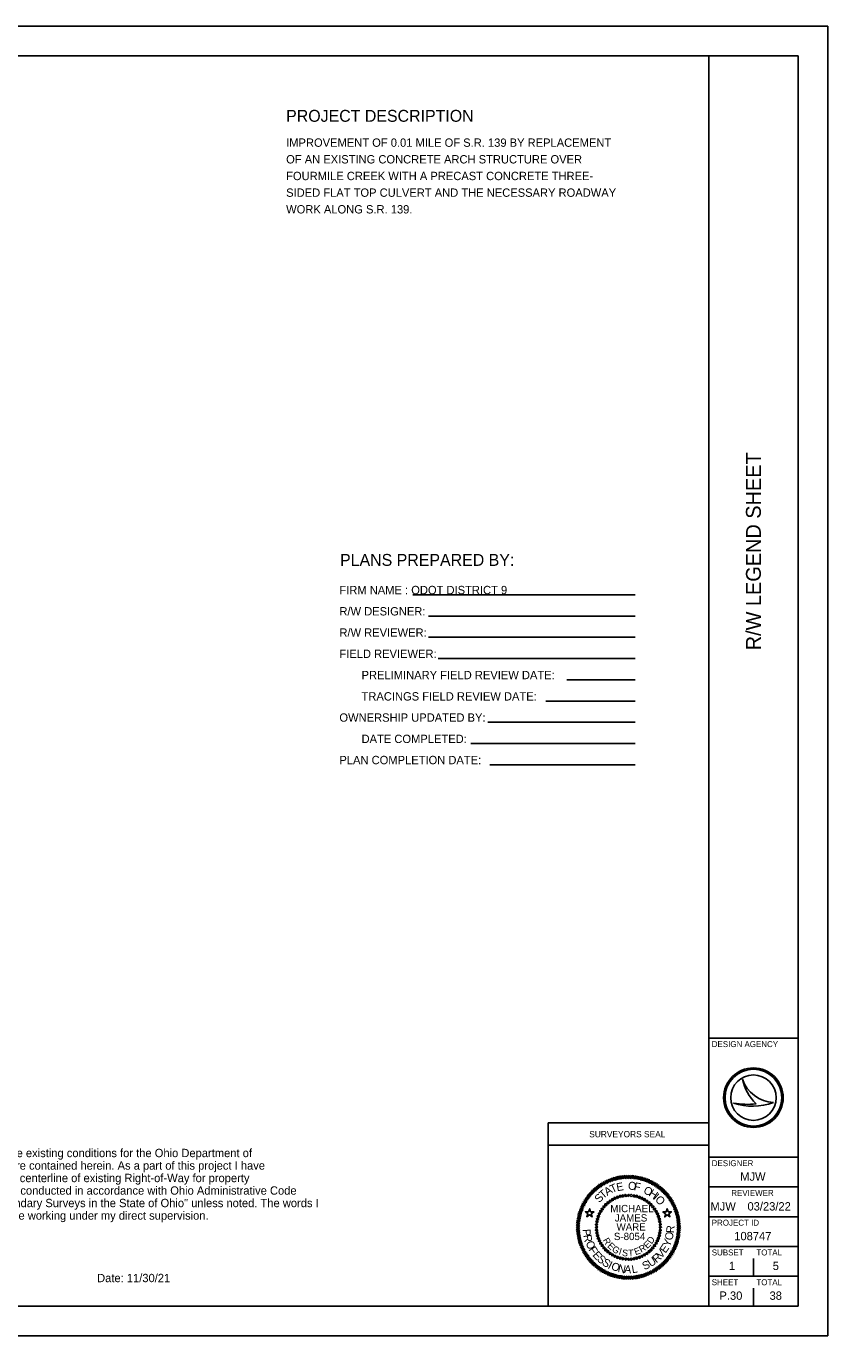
# Model space of a CAD drawing. Extents: x 0 to 34, y -5.8 to 22.
# Drawn here: x 20.53 to 34, y 0 to 22 of the extents above; entities that cross this region are included whole.
import ezdxf

# ---------------------------------------------------------------- set-up
doc = ezdxf.new("R2010")
doc.units = 0
for name, color, linetype in [('SH_Border', 7, 'Continuous'), ('SH_Cut_Line', 7, 'Continuous'), ('SH_Data', 7, 'Continuous'), ('SH_Text', 7, 'Continuous')]:
    doc.layers.add(name, color=color, linetype=linetype)

msp = doc.modelspace()

# ---------------------------------------------------------------- linework, layer by layer
at = {"layer": 'SH_Border'}
for p, q in [((32, 0.5), (32, 21.5)), ((32, 5), (33.5, 5)), ((32, 3), (33.5, 3)), ((32, 2.5), (33.5, 2.5)), ((32, 2), (33.5, 2)), ((32, 1.5), (33.5, 1.5)), ((32, 1), (33.5, 1))]:
    msp.add_line(p, q, dxfattribs=at)
msp.add_lwpolyline([(1.5, 21.5), (33.5, 21.5), (33.5, 0.5), (1.5, 0.5)], close=True, dxfattribs=at)
at = {"layer": 'SH_Cut_Line'}
msp.add_lwpolyline([(0, 0), (34, 0), (34, 22), (0, 22)], close=True, dxfattribs=at)
at = {"layer": 'SH_Data'}
for p, q in [((32.567, 4.31), (32.567, 4.31)), ((32.75, 4), (32.75, 4)), ((32.417, 3.91), (32.417, 3.91)), ((33.087, 3.919), (33.087, 3.919)), ((29.3, 3.2), (32, 3.2)), ((32.75, 1), (32.75, 1.3)), ((32.375, 0.675), (32.375, 0.675)), ((32.75, 0.5), (32.75, 0.8))]:
    msp.add_line(p, q, dxfattribs=at)
msp.add_lwpolyline([(29.3, 3.575), (32, 3.575), (32, 0.5), (29.3, 0.5)], close=True, dxfattribs=at)
for radius in [0.5, 0.477, 0.477, 0.382]:
    msp.add_circle((32.75, 4), radius, dxfattribs=at)
for centre, radius, start, end in [((33.116, 4.498), 0.58, 198.9257, 198.9319), ((33.347, 4.47), 0.796, 191.6379, 191.6421), ((33.116, 4.498), 0.58, 198.9319, 267.1657), ((33.347, 4.47), 0.796, 191.6421, 226.0947), ((32.739, 4.87), 1.013, 251.4576, 290.0832), ((32.648, 5.154), 1.266, 259.4964, 259.4995), ((32.739, 4.87), 1.013, 251.4527, 251.4576), ((32.648, 5.154), 1.266, 259.4995, 276.6672)]:
    msp.add_arc(centre, radius, start, end, dxfattribs=at)
at = {"layer": 'SH_Text'}
for p, q in [((27.026, 12.449), (30.763, 12.449)), ((27.29, 12.091), (30.763, 12.091)), ((27.29, 11.734), (30.763, 11.734)), ((27.454, 11.377), (30.763, 11.377)), ((29.617, 11.02), (30.763, 11.02)), ((29.26, 10.663), (30.763, 10.663)), ((28.29, 10.306), (30.763, 10.306)), ((28.004, 9.948), (30.763, 9.948)), ((28.319, 9.592), (30.763, 9.592)), ((30.381, 2.593), (30.338, 2.644)), ((30.408, 2.602), (30.367, 2.655)), ((30.436, 2.61), (30.396, 2.664)), ((30.463, 2.617), (30.426, 2.672)), ((30.491, 2.623), (30.456, 2.68)), ((30.519, 2.628), (30.486, 2.686)), ((30.547, 2.632), (30.516, 2.691)), ((30.576, 2.635), (30.546, 2.695)), ((30.604, 2.637), (30.577, 2.698)), ((30.633, 2.638), (30.608, 2.7)), ((30.661, 2.638), (30.638, 2.701)), ((30.69, 2.638), (30.669, 2.701)), ((30.718, 2.636), (30.699, 2.7)), ((30.746, 2.633), (30.73, 2.698)), ((30.774, 2.629), (30.761, 2.694)), ((30.803, 2.624), (30.791, 2.69)), ((30.83, 2.618), (30.821, 2.684)), ((30.858, 2.611), (30.851, 2.678)), ((30.885, 2.604), (30.881, 2.67)), ((30.913, 2.595), (30.91, 2.662)), ((30.939, 2.585), (30.939, 2.652)), ((30.966, 2.575), (30.968, 2.642)), ((30.071, 2.398), (30.01, 2.425)), ((30.091, 2.417), (30.031, 2.447)), ((30.112, 2.437), (30.053, 2.468)), ((30.134, 2.455), (30.076, 2.488)), ((30.156, 2.473), (30.1, 2.508)), ((30.179, 2.489), (30.124, 2.527)), ((30.203, 2.505), (30.149, 2.545)), ((30.227, 2.521), (30.174, 2.562)), ((30.252, 2.535), (30.2, 2.578)), ((30.277, 2.548), (30.227, 2.593)), ((30.302, 2.561), (30.254, 2.607)), ((30.328, 2.573), (30.282, 2.621)), ((30.355, 2.583), (30.31, 2.633)), ((30.992, 2.563), (30.997, 2.63)), ((31.018, 2.551), (31.025, 2.617)), ((31.043, 2.538), (31.052, 2.604)), ((31.067, 2.523), (31.079, 2.589)), ((31.092, 2.508), (31.106, 2.574)), ((31.115, 2.493), (31.132, 2.557)), ((31.138, 2.476), (31.157, 2.54)), ((31.161, 2.458), (31.182, 2.522)), ((31.183, 2.44), (31.206, 2.503)), ((31.204, 2.421), (31.229, 2.483)), ((31.225, 2.402), (31.252, 2.463)), ((31.244, 2.381), (31.274, 2.441)), ((29.935, 2.216), (29.868, 2.225)), ((29.949, 2.24), (29.883, 2.252)), ((29.964, 2.265), (29.898, 2.279)), ((29.98, 2.288), (29.915, 2.304)), ((29.996, 2.311), (29.932, 2.33)), ((30.014, 2.334), (29.95, 2.355)), ((30.032, 2.356), (29.969, 2.379)), ((30.051, 2.377), (29.989, 2.402)), ((31.264, 2.36), (31.295, 2.419)), ((31.282, 2.338), (31.315, 2.396)), ((31.3, 2.316), (31.335, 2.373)), ((31.316, 2.293), (31.354, 2.348)), ((31.332, 2.269), (31.372, 2.323)), ((31.348, 2.245), (31.389, 2.298)), ((31.362, 2.221), (31.405, 2.272)), ((31.375, 2.195), (31.42, 2.245)), ((31.388, 2.17), (31.434, 2.218)), ((29.854, 2.003), (29.788, 1.994)), ((29.861, 2.031), (29.794, 2.024)), ((29.868, 2.058), (29.802, 2.054)), ((29.877, 2.086), (29.81, 2.083)), ((29.887, 2.112), (29.82, 2.112)), ((29.897, 2.139), (29.831, 2.141)), ((29.909, 2.165), (29.842, 2.17)), ((29.921, 2.19), (29.855, 2.197)), ((31.4, 2.144), (31.448, 2.19)), ((31.41, 2.118), (31.46, 2.162)), ((31.42, 2.091), (31.471, 2.134)), ((31.429, 2.064), (31.482, 2.105)), ((31.437, 2.036), (31.491, 2.076)), ((31.444, 2.009), (31.499, 2.046)), ((31.45, 1.981), (31.507, 2.016)), ((31.455, 1.953), (31.513, 1.986)), ((29.835, 1.862), (29.771, 1.842)), ((29.834, 1.834), (29.771, 1.811)), ((29.836, 1.891), (29.772, 1.872)), ((29.834, 1.805), (29.772, 1.78)), ((29.839, 1.919), (29.774, 1.903)), ((29.835, 1.777), (29.774, 1.75)), ((29.843, 1.947), (29.778, 1.934)), ((29.848, 1.975), (29.782, 1.964)), ((31.459, 1.925), (31.518, 1.956)), ((31.462, 1.896), (31.522, 1.926)), ((31.463, 1.754), (31.527, 1.773)), ((31.464, 1.868), (31.525, 1.895)), ((31.465, 1.84), (31.527, 1.865)), ((31.465, 1.783), (31.528, 1.803)), ((31.466, 1.811), (31.528, 1.834)), ((29.837, 1.749), (29.777, 1.719)), ((29.84, 1.72), (29.781, 1.689)), ((29.844, 1.692), (29.786, 1.659)), ((29.849, 1.664), (29.792, 1.629)), ((29.855, 1.636), (29.8, 1.599)), ((29.862, 1.609), (29.808, 1.569)), ((29.87, 1.581), (29.817, 1.54)), ((29.879, 1.554), (29.828, 1.511)), ((31.422, 1.56), (31.489, 1.562)), ((31.431, 1.587), (31.497, 1.591)), ((31.439, 1.614), (31.505, 1.621)), ((31.445, 1.642), (31.512, 1.651)), ((31.451, 1.67), (31.517, 1.681)), ((31.456, 1.698), (31.521, 1.712)), ((31.46, 1.726), (31.525, 1.742)), ((29.889, 1.527), (29.839, 1.483)), ((29.9, 1.501), (29.851, 1.455)), ((29.911, 1.475), (29.865, 1.427)), ((29.924, 1.45), (29.879, 1.4)), ((29.937, 1.424), (29.894, 1.373)), ((29.952, 1.4), (29.91, 1.347)), ((29.967, 1.376), (29.927, 1.322)), ((29.983, 1.352), (29.945, 1.297)), ((30, 1.329), (29.964, 1.273)), ((31.303, 1.334), (31.367, 1.315)), ((31.32, 1.357), (31.385, 1.341)), ((31.335, 1.38), (31.401, 1.367)), ((31.35, 1.405), (31.416, 1.393)), ((31.365, 1.429), (31.431, 1.42)), ((31.378, 1.455), (31.444, 1.448)), ((31.39, 1.48), (31.457, 1.476)), ((31.402, 1.506), (31.469, 1.504)), ((31.412, 1.533), (31.479, 1.533)), ((30.017, 1.307), (29.984, 1.249)), ((30.036, 1.285), (30.004, 1.226)), ((30.055, 1.264), (30.025, 1.204)), ((30.075, 1.244), (30.047, 1.182)), ((30.095, 1.224), (30.07, 1.162)), ((30.116, 1.205), (30.094, 1.142)), ((30.138, 1.187), (30.118, 1.123)), ((30.161, 1.169), (30.142, 1.105)), ((30.184, 1.152), (30.168, 1.088)), ((30.208, 1.137), (30.194, 1.071)), ((30.232, 1.122), (30.22, 1.056)), ((30.256, 1.107), (30.247, 1.041)), ((31.048, 1.11), (31.099, 1.067)), ((31.072, 1.125), (31.125, 1.083)), ((31.096, 1.14), (31.15, 1.1)), ((31.12, 1.156), (31.175, 1.118)), ((31.143, 1.173), (31.2, 1.137)), ((31.165, 1.19), (31.223, 1.157)), ((31.187, 1.209), (31.246, 1.177)), ((31.208, 1.228), (31.268, 1.198)), ((31.229, 1.248), (31.29, 1.22)), ((31.248, 1.268), (31.31, 1.243)), ((31.267, 1.289), (31.33, 1.266)), ((31.286, 1.311), (31.349, 1.291)), ((30.282, 1.094), (30.275, 1.028)), ((30.307, 1.082), (30.303, 1.015)), ((30.333, 1.07), (30.331, 1.003)), ((30.36, 1.06), (30.36, 0.993)), ((30.387, 1.05), (30.389, 0.983)), ((30.414, 1.041), (30.418, 0.975)), ((30.441, 1.034), (30.448, 0.967)), ((30.469, 1.027), (30.478, 0.961)), ((30.497, 1.021), (30.508, 0.955)), ((30.525, 1.016), (30.539, 0.951)), ((30.553, 1.012), (30.569, 0.947)), ((30.581, 1.009), (30.6, 0.945)), ((30.61, 1.008), (30.63, 0.944)), ((30.638, 1.007), (30.661, 0.944)), ((30.667, 1.007), (30.692, 0.945)), ((30.695, 1.008), (30.722, 0.947)), ((30.724, 1.01), (30.753, 0.95)), ((30.752, 1.013), (30.783, 0.954)), ((30.78, 1.017), (30.813, 0.959)), ((30.808, 1.022), (30.843, 0.965)), ((30.836, 1.028), (30.873, 0.973)), ((30.864, 1.035), (30.903, 0.981)), ((30.891, 1.043), (30.932, 0.99)), ((30.918, 1.052), (30.961, 1.001)), ((30.945, 1.062), (30.989, 1.012)), ((30.971, 1.072), (31.017, 1.024)), ((30.997, 1.084), (31.045, 1.038)), ((31.023, 1.097), (31.072, 1.052))]:
    msp.add_line(p, q, dxfattribs=at)
for points in [[(30.285, 2.187), (30.285, 2.216), (30.256, 2.216), (30.256, 2.187)], [(30.318, 2.218), (30.32, 2.246), (30.292, 2.249), (30.29, 2.22)], [(30.354, 2.245), (30.358, 2.273), (30.331, 2.278), (30.326, 2.25)], [(30.392, 2.269), (30.399, 2.297), (30.372, 2.304), (30.364, 2.277)], [(30.431, 2.29), (30.441, 2.317), (30.415, 2.327), (30.405, 2.3)], [(30.473, 2.308), (30.485, 2.333), (30.459, 2.345), (30.447, 2.319)], [(30.516, 2.321), (30.53, 2.346), (30.506, 2.36), (30.492, 2.335)], [(30.56, 2.331), (30.576, 2.354), (30.553, 2.37), (30.537, 2.347)], [(30.605, 2.337), (30.623, 2.358), (30.601, 2.377), (30.583, 2.355)], [(30.65, 2.339), (30.67, 2.359), (30.65, 2.379), (30.63, 2.359)], [(30.695, 2.337), (30.716, 2.355), (30.698, 2.377), (30.676, 2.358)], [(30.739, 2.331), (30.762, 2.347), (30.746, 2.37), (30.723, 2.354)], [(30.783, 2.321), (30.808, 2.335), (30.794, 2.36), (30.769, 2.346)], [(30.826, 2.308), (30.852, 2.319), (30.84, 2.345), (30.814, 2.333)], [(30.868, 2.29), (30.894, 2.3), (30.885, 2.327), (30.858, 2.317)], [(30.908, 2.269), (30.935, 2.277), (30.928, 2.304), (30.9, 2.297)], [(30.946, 2.245), (30.973, 2.25), (30.969, 2.278), (30.941, 2.273)], [(30.981, 2.218), (31.01, 2.22), (31.007, 2.249), (30.979, 2.246)], [(31.015, 2.187), (31.043, 2.187), (31.043, 2.216), (31.015, 2.216)], [(30.015, 2.082), (30.07, 2.08), (30.024, 2.049), (30.04, 1.997), (29.996, 2.03), (29.951, 2), (29.97, 2.051), (29.927, 2.085), (29.981, 2.083), (30, 2.134)], [(30.151, 1.956), (30.137, 1.981), (30.112, 1.966), (30.127, 1.942)], [(30.165, 1.999), (30.153, 2.025), (30.127, 2.013), (30.139, 1.987)], [(30.182, 2.041), (30.172, 2.067), (30.146, 2.058), (30.155, 2.031)], [(30.203, 2.081), (30.195, 2.108), (30.168, 2.101), (30.175, 2.073)], [(30.227, 2.119), (30.222, 2.146), (30.194, 2.141), (30.199, 2.114)], [(30.254, 2.154), (30.252, 2.182), (30.224, 2.18), (30.226, 2.152)], [(31.045, 2.154), (31.073, 2.152), (31.076, 2.18), (31.047, 2.182)], [(31.072, 2.119), (31.1, 2.114), (31.105, 2.141), (31.077, 2.146)], [(31.097, 2.081), (31.124, 2.073), (31.131, 2.101), (31.104, 2.108)], [(31.117, 2.041), (31.144, 2.031), (31.154, 2.058), (31.127, 2.067)], [(31.135, 1.999), (31.16, 1.987), (31.172, 2.013), (31.147, 2.025)], [(31.148, 1.956), (31.173, 1.942), (31.187, 1.966), (31.162, 1.981)], [(31.303, 2.03), (31.26, 1.997), (31.275, 2.049), (31.229, 2.08), (31.284, 2.082), (31.299, 2.134), (31.318, 2.083), (31.373, 2.085), (31.329, 2.051), (31.348, 2)], [(30.134, 1.823), (30.114, 1.843), (30.094, 1.823), (30.114, 1.803)], [(30.135, 1.868), (30.117, 1.889), (30.096, 1.871), (30.114, 1.849)], [(30.135, 1.778), (30.114, 1.796), (30.096, 1.774), (30.117, 1.756)], [(30.141, 1.912), (30.125, 1.935), (30.102, 1.919), (30.118, 1.896)], [(31.158, 1.912), (31.181, 1.896), (31.197, 1.919), (31.174, 1.935)], [(31.164, 1.868), (31.185, 1.849), (31.204, 1.871), (31.182, 1.889)], [(31.164, 1.778), (31.182, 1.756), (31.204, 1.774), (31.185, 1.796)], [(31.166, 1.823), (31.186, 1.803), (31.206, 1.823), (31.186, 1.843)], [(30.141, 1.733), (30.118, 1.749), (30.102, 1.726), (30.125, 1.71)], [(30.151, 1.689), (30.127, 1.703), (30.112, 1.679), (30.137, 1.664)], [(30.165, 1.646), (30.139, 1.658), (30.127, 1.632), (30.153, 1.62)], [(30.182, 1.604), (30.155, 1.614), (30.146, 1.588), (30.172, 1.578)], [(30.203, 1.564), (30.175, 1.572), (30.168, 1.544), (30.195, 1.537)], [(31.097, 1.564), (31.104, 1.537), (31.131, 1.544), (31.124, 1.572)], [(31.117, 1.604), (31.127, 1.578), (31.154, 1.588), (31.144, 1.614)], [(31.135, 1.646), (31.147, 1.62), (31.172, 1.632), (31.16, 1.658)], [(31.148, 1.689), (31.162, 1.664), (31.187, 1.679), (31.173, 1.703)], [(31.158, 1.733), (31.174, 1.71), (31.197, 1.726), (31.181, 1.749)], [(30.227, 1.527), (30.199, 1.531), (30.194, 1.504), (30.222, 1.499)], [(30.254, 1.491), (30.226, 1.493), (30.224, 1.465), (30.252, 1.463)], [(30.285, 1.458), (30.256, 1.458), (30.256, 1.429), (30.285, 1.429)], [(30.318, 1.427), (30.29, 1.425), (30.292, 1.397), (30.32, 1.399)], [(30.354, 1.4), (30.326, 1.395), (30.331, 1.367), (30.358, 1.372)], [(30.392, 1.376), (30.364, 1.368), (30.372, 1.341), (30.399, 1.348)], [(30.431, 1.355), (30.405, 1.345), (30.415, 1.319), (30.441, 1.328)], [(30.473, 1.338), (30.447, 1.326), (30.459, 1.3), (30.485, 1.312)], [(30.516, 1.324), (30.492, 1.31), (30.506, 1.285), (30.53, 1.3)], [(30.783, 1.324), (30.769, 1.3), (30.794, 1.285), (30.808, 1.31)], [(30.826, 1.338), (30.814, 1.312), (30.84, 1.3), (30.852, 1.326)], [(30.868, 1.355), (30.858, 1.328), (30.885, 1.319), (30.894, 1.345)], [(30.908, 1.376), (30.9, 1.348), (30.928, 1.341), (30.935, 1.368)], [(30.946, 1.4), (30.941, 1.372), (30.969, 1.367), (30.973, 1.395)], [(30.981, 1.427), (30.979, 1.399), (31.007, 1.397), (31.01, 1.425)], [(31.015, 1.458), (31.015, 1.429), (31.043, 1.429), (31.043, 1.458)], [(31.045, 1.491), (31.047, 1.463), (31.076, 1.465), (31.073, 1.493)], [(31.072, 1.527), (31.077, 1.499), (31.105, 1.504), (31.1, 1.531)], [(30.56, 1.314), (30.537, 1.298), (30.553, 1.275), (30.576, 1.291)], [(30.605, 1.308), (30.583, 1.29), (30.601, 1.269), (30.623, 1.287)], [(30.65, 1.306), (30.63, 1.286), (30.65, 1.266), (30.67, 1.286)], [(30.695, 1.308), (30.676, 1.287), (30.698, 1.269), (30.716, 1.29)], [(30.739, 1.314), (30.723, 1.291), (30.746, 1.275), (30.762, 1.298)]]:
    msp.add_lwpolyline(points, close=True, dxfattribs=at)
for points in [[(29.97, 2.051), (29.951, 2), (29.996, 2.03), (30.04, 1.997), (30.024, 2.049), (30.07, 2.08), (30.015, 2.082), (30, 2.134), (29.981, 2.083), (29.927, 2.085), (29.97, 2.051)], [(31.318, 2.083), (31.299, 2.134), (31.284, 2.082), (31.229, 2.08), (31.275, 2.049), (31.26, 1.997), (31.303, 2.03), (31.348, 2), (31.329, 2.051), (31.373, 2.085), (31.318, 2.083)]]:
    msp.add_lwpolyline(points, dxfattribs=at)
for radius in [0.857, 0.837]:
    msp.add_circle((30.65, 1.823), radius, dxfattribs=at)

# ---------------------------------------------------------------- texts
at = {"layer": 'SH_Data'}
msp.add_text('R/W LEGEND SHEET', height=0.25, rotation=90, dxfattribs=at).set_placement((32.875, 11.516))
for s, height, p in [('DESIGN AGENCY', 0.1, (32.05, 4.85)), ('SURVEYORS SEAL', 0.105, (29.991, 3.335)), ('DESIGNER', 0.1, (32.05, 2.85)), ('MJW', 0.14, (32.528, 2.605)), ('REVIEWER', 0.1, (32.378, 2.35)), ('MJW', 0.14, (32.028, 2.105)), ('03/23/22', 0.14, (32.65, 2.105)), ('PROJECT ID', 0.1, (32.05, 1.85)), ('SUBSET', 0.1, (32.05, 1.35)), ('TOTAL', 0.1, (32.8, 1.35)), ('1', 0.14, (32.339, 1.105)), ('5', 0.14, (33.075, 1.105)), ('SHEET', 0.1, (32.05, 0.85)), ('TOTAL', 0.1, (32.8, 0.85)), ('P.30', 0.14, (32.179, 0.605)), ('38', 0.14, (33.021, 0.605))]:
    msp.add_text(s, height=height, dxfattribs=at).set_placement(p)
at = {"layer": 'SH_Text'}
for s, height, p in [('PROJECT DESCRIPTION', 0.2, (24.899, 20.394)), ('IMPROVEMENT OF 0.01 MILE OF S.R. 139 BY REPLACEMENT ', 0.14, (24.899, 19.974)), ('OF AN EXISTING CONCRETE ARCH STRUCTURE OVER ', 0.14, (24.899, 19.694)), ('FOURMILE CREEK WITH A PRECAST CONCRETE THREE-', 0.14, (24.899, 19.414)), ('SIDED FLAT TOP CULVERT AND THE NECESSARY ROADWAY ', 0.14, (24.899, 19.134)), ('WORK ALONG S.R. 139.', 0.14, (24.899, 18.854)), ('PLANS PREPARED BY:', 0.2, (25.805, 12.934)), ('FIRM NAME : ODOT DISTRICT 9', 0.14, (25.794, 12.458)), ('R/W DESIGNER:', 0.14, (25.794, 12.101)), ('R/W REVIEWER:', 0.14, (25.794, 11.744)), ('FIELD REVIEWER:', 0.14, (25.794, 11.387)), ('PRELIMINARY FIELD REVIEW DATE:', 0.14, (26.166, 11.03)), ('TRACINGS FIELD REVIEW DATE:', 0.14, (26.166, 10.672)), ('OWNERSHIP UPDATED BY:', 0.14, (25.794, 10.316)), ('DATE COMPLETED:', 0.14, (26.166, 9.958)), ('PLAN COMPLETION DATE:', 0.14, (25.794, 9.602)), ('I, Michael James Ware, P.S., have conducted a survey of the existing conditions for the Ohio Department of', 0.14, (15.407, 3.001)), ('Transportation in October 2020. The results of that survey are contained herein. As a part of this project I have', 0.14, (15.407, 2.791)), ('reestablished the locations of the existing property lines and centerline of existing Right-of-Way for property', 0.14, (15.407, 2.581)), ('takes contained herein. All of my work contained herein was conducted in accordance with Ohio Administrative Code', 0.14, (15.407, 2.371)), ('4733-37, commonly known as "Minimum Standards for Boundary Surveys in the State of Ohio" unless noted. The words I', 0.14, (15.407, 2.161)), ('MICHAEL', 0.1223, (30.345, 2.077)), ('and my as used herein are to mean either myself or someone working under my direct supervision.', 0.14, (15.407, 1.951)), ('JAMES', 0.1223, (30.421, 1.92)), ('WARE', 0.1223, (30.45, 1.768)), ('S-8054', 0.1223, (30.406, 1.608)), ('108747', 0.14, (32.428, 1.605)), ('Michael James Ware, Professional Land Surveyor No. 8054                          Date: 11/30/21', 0.14, (15.407, 0.901))]:
    msp.add_text(s, height=height, dxfattribs=at).set_placement(p)
for s, height, rotation, p in [('T', 0.134, 40.6194, (30.225, 2.294)), ('A', 0.134, 33.1554, (30.293, 2.348)), ('T', 0.134, 25.6914, (30.378, 2.396)), ('E', 0.134, 10.7635, (30.46, 2.427)), ('O', 0.134, 355.8356, (30.64, 2.457)), ('F', 0.134, 348.3716, (30.735, 2.45)), ('O', 0.134, 333.4437, (30.891, 2.403)), ('H', 0.134, 325.9797, (30.98, 2.362)), ('S', 0.134, 48.0833, (30.164, 2.226)), ('I', 0.134, 318.5158, (31.055, 2.304)), ('O', 0.134, 311.0518, (31.089, 2.284)), ('P', 0.134, 272.8671, (29.879, 1.791)), ('R', 0.134, 84.5383, (31.415, 1.72)), ('R', 0.134, 280.3311, (29.892, 1.689)), ('O', 0.134, 295.259, (29.926, 1.56)), ('R', 0.112, 299.3103, (30.215, 1.608)), ('E', 0.112, 317.124, (30.287, 1.499)), ('E', 0.112, 46.1922, (30.97, 1.455)), ('D', 0.112, 55.099, (31.041, 1.533)), ('E', 0.134, 54.6824, (31.273, 1.378)), ('Y', 0.134, 69.6103, (31.345, 1.485)), ('O', 0.134, 77.0743, (31.386, 1.595)), ('F', 0.134, 302.723, (29.974, 1.448)), ('E', 0.134, 310.1869, (30.039, 1.353)), ('S', 0.134, 317.6509, (30.11, 1.275)), ('G', 0.112, 326.0308, (30.361, 1.431)), ('I', 0.112, 343.8444, (30.48, 1.37)), ('S', 0.112, 352.7513, (30.538, 1.343)), ('T', 0.112, 1.6581, (30.647, 1.336)), ('E', 0.112, 19.4717, (30.769, 1.353)), ('R', 0.112, 28.3786, (30.864, 1.394)), ('U', 0.134, 32.2905, (31.023, 1.151)), ('R', 0.134, 39.7545, (31.12, 1.217)), ('V', 0.134, 47.2185, (31.199, 1.289)), ('S', 0.134, 325.1149, (30.195, 1.203)), ('I', 0.134, 332.5788, (30.293, 1.139)), ('O', 0.134, 340.0428, (30.348, 1.118)), ('N', 0.134, 347.5067, (30.463, 1.074)), ('A', 0.134, 354.9707, (30.575, 1.057)), ('L', 0.134, 9.8986, (30.715, 1.05)), ('S', 0.134, 24.8266, (30.918, 1.101))]:
    msp.add_text(s, height=height, rotation=rotation, dxfattribs=at).set_placement(p)

doc.saveas('drawing.dxf')
